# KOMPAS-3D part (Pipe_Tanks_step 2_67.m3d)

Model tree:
1. X Axis
2. Y Axis
3. Z Axis  (labels: Valve Dy 50; Pipe Dn 50)
     Òîëùèíà ñòåíêè 1 = 1

Referenced files in C:\Documents and Settings\kashirsky\Мои документы\Camtasia Studio\Pipelines3D\Tanks\: Tanks_step 2.a3d
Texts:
  Pipe Dn 50
  Steel ASTM A295
  Three Point Plane
  Plane at Angle
  Line and Point Plane
  Axis through Two Vertices
  Axis of Feature
  Axis of Conical Surface
  Axis through Edge
  Trim by Surface
  Trim by Sketch
  Feature with No History
  Intersection Axis of Two Planes
  Two Line Plane
  Line and Face Plane
  Bend by line
  Hole in sheet body
  Cut in sheet body
  Point in CM
  Linear Dimension from Line to Point
  Surface Finish Symbol
  Geometric Tolerance Symbol
  Leader #1
  Leader #2
  Leader #3
  Shape Deviations and Datum
  Node point number
  Mark of coordination axis
  Node point designation
  Mark/Reference designation with leader
  Mark/reference designation on line
  Mark/Reference designation without leader
  Valve Dy 50
  Plane of section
